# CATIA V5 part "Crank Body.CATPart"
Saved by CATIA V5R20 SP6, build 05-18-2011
Part number: Crank Body
Bounding box of the stored display mesh (mm): x -38.5 to 8.5, y -13.73 to 13.732, z -35 to 6
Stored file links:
  E:\#01 CATIA Lecture Materials\#06 DMU\#03 DMU Page01 KIN EX03\Crank Body.CATPart
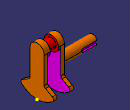
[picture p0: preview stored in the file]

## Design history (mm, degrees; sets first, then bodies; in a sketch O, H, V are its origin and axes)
Set1 "Reference Data"
  Point1 "Center Point": (0, 0, 0)
  Plane1 "Plane.1(XY Offset=-15mm)": type Offset, RefPlane xy-plane, Offset 15, reversed
  Plane2 "Plane.2(Solid Side Offset=30mm)": type Offset, RefPlane start face of Pad1, Offset 30, reversed
  Point2 "Middle Point": type OnCurve, Support edge [face of Pad1 from Sketch1.A2 | end face of Pad1], Ratio 0.5
Body1 (main body)
  Body2
    Sketch1 on yz-plane, origin (0, 0, 0), H (0, 1, 0), V (0, 0, 1)
      arc A1 centre (0, 0) radius 6 from (6, 0) to (-6, 0) ccw
      arc A2 centre (0, -15) radius 20 from (-15, -28.2288) to (15, -28.2288) ccw
      point P1 (0, -15)
      point P2 (-6, 0)
      line L1 (-6, 0) -> (-6, -23.0326)
      point P3 (-6, -23.0326)
      line L2 (-6, -23.0326) -> (-15, -28.2288)
      point P4 (-15, -28.2288)
      point P5 (6, -23.0326)
      line L3 (6, 0) -> (6, -23.0326)
      line L4 (6, -23.0326) -> (15, -28.2288)
      point P7 (15, -28.2288)
      reference intersected line E1 through (0, -15) direction (-1, 0) from Plane1
      distance L3 L1 = 12
      angle L2 L4 = 120
      distance P4 P7 = 30
      radius A2 = 20
      coincidence: P1 V, P2 A1, P2 H, P4 A2, P4 L2, P2 L1, P1 E1
      tangency: L1 A1
      symmetry: P3 P5 V, L1 L3 V, L2 L4 V
    Pad1: profile Sketch1, direction (1, 0, 0), length 8.5, mirrored extent
    Fillet1: radius 2, on edge [face of Pad1 from Sketch1.L3 | face of Pad1 from Sketch1.L4]; edge [face of Pad1 from Sketch1.L2 | face of Pad1 from Sketch1.L1]; edge [face of Pad1 from Sketch1.A2 | face of Pad1 from Sketch1.L2]; edge [face of Pad1 from Sketch1.L4 | face of Pad1 from Sketch1.A2]
  Assemble1: tool Body2
  Body3 "Pocket Body"
    Sketch2 on yz-plane, origin (0, 0, 0), H (0, 1, 0), V (0, 0, 1)
      arc A1 centre (0, 0) radius 6 from (-6, 0) to (6, 0) ccw
      radius A1 = 6
    Pad2: profile Sketch2, direction (1, 0, 0), length 5.5, mirrored extent
  Remove1: tool Body3
  Body4 "Hole Body"
    Sketch3 on yz-plane, origin (0, 0, 0), H (0, 1, 0), V (0, 0, 1)
      circle A1 centre (0, 0) radius 4
      projected arc E1 centre (0, 0) radius 6 from (6, 0) to (-6, 0) ccw from edge [face of Pad1 from Sketch1.A1 | end face of Pad1]
      projected circle E2 centre (0, 0) radius 6 from edge [face of Pad1 from Sketch1.A1 | end face of Pad1]
      point P1 (6, 0)
      point P3 (6, 0)
      radius A1 = 4
      coincidence: P1 P3
    Pad3: profile Sketch3, direction (1, 0, 0), length 3.5, mirrored extent
  Remove2: tool Body4
  Body5 "Hole Boss Body"
    Sketch4 on yz-plane, origin (0, 0, 0), H (0, 1, 0), V (0, 0, 1)
      circle A1 centre (0, -15) radius 4
      point P1 (0, -15)
      reference intersected line E1 through (0, -15) direction (-1, 0) from Plane1
      radius A1 = 4
      coincidence: P1 V, P1 E1
    Pad4: profile Sketch4, direction (-1, 0, 0), up to Plane2, opposite side length -8.5
    Body6 "Key Hole Body"
      Sketch5 on zx-plane, origin (0, 0, 0), H (-1, 0, 0), V (0, 0, 1)
        construction line L1 (23.7462, -15) -> (38.3022, -15)
        reference intersected line E1 through (0, -15) direction (-1, 0) from Plane1
        line L2 (38.5, -13.5) -> (26.5, -13.5)
        arc A1 centre (26.5, -15) radius 1.5 from (26.5, -13.5) to (26.5, -16.5) ccw
        point P5 (26.5, -15)
        line L3 (26.5, -16.5) -> (38.5, -16.5)
        line L4 (38.5, -16.5) -> (38.5, -13.5)
        reference intersected line E2 through (38.5, 0) direction (0, -1) from Plane2
        distance L2 L3 = 3
        distance L4 P5 = 12
        horizontal: L1 H, L2 H
        coincidence: L1 E1, E2 L4
        tangency: A1 L2, L3 A1
        vertical: L4 V
        symmetry: L2 L3 L1
      Pad5: profile Sketch5, direction (0, 1, 0), length 5, opposite side length -2.2
    Remove3: tool Body6
  Assemble2: tool Body5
